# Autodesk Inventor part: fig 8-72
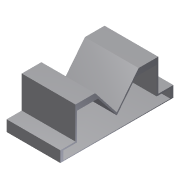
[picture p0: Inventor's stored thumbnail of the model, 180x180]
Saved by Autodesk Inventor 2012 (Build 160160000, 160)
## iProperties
Shininess: 77.0
Length Units: 11269
Angle Units: 11279
Time Units: 11290
Mass Units: 11283
Length Display Precision: 3
Angle Display Precision: 2
Created: 2002-01
Part Number: fig 8-72
Document SubType Name: Modeling
Designer: ***
Density: 1 g/cm^3
Material: Default
Density: 0.0
Volumn: 0.0
Area: 0.0
PropertySet Name: Model Information
Control State: 0
Master: False
Checked Out: False
Author: ***
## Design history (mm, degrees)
node "Sketch1"
sketch "Sketch2"
  geometry: L1 (0, 0)-(-14.184, 17.961); L2 (-14.184, 17.961)-(-26.987, 17.961); L3 (-26.987, 17.961)-(-26.987, -2.947); L4 (-26.987, -2.947)-(-36.842, -2.947); L5 (-36.842, -2.947)-(-36.842, -10.132); L6 (26.987, 17.961)-(26.987, -2.947); L7 (14.184, 17.961)-(26.987, 17.961); L8 (26.987, -2.947)-(36.842, -2.947); L9 (36.842, -10.132)-(-36.842, -10.132); L10 (36.842, -2.947)-(36.842, -10.132); L11 (0, 0)-(14.184, 17.961)
  constraints: 22 end point, 2 horizontal, 2 parallel, 1 perpendicular
extrude "Extrusion1" new body sketch "Sketch2" distance "d0" = 35; taper "d1" = 0 deg
shell "Shell3" dims "d8" = 4, "d9" = 4, "d10" = 2, "d11" = 2, "d12" = 0.5, "d13" = 1
body "Solid1"
